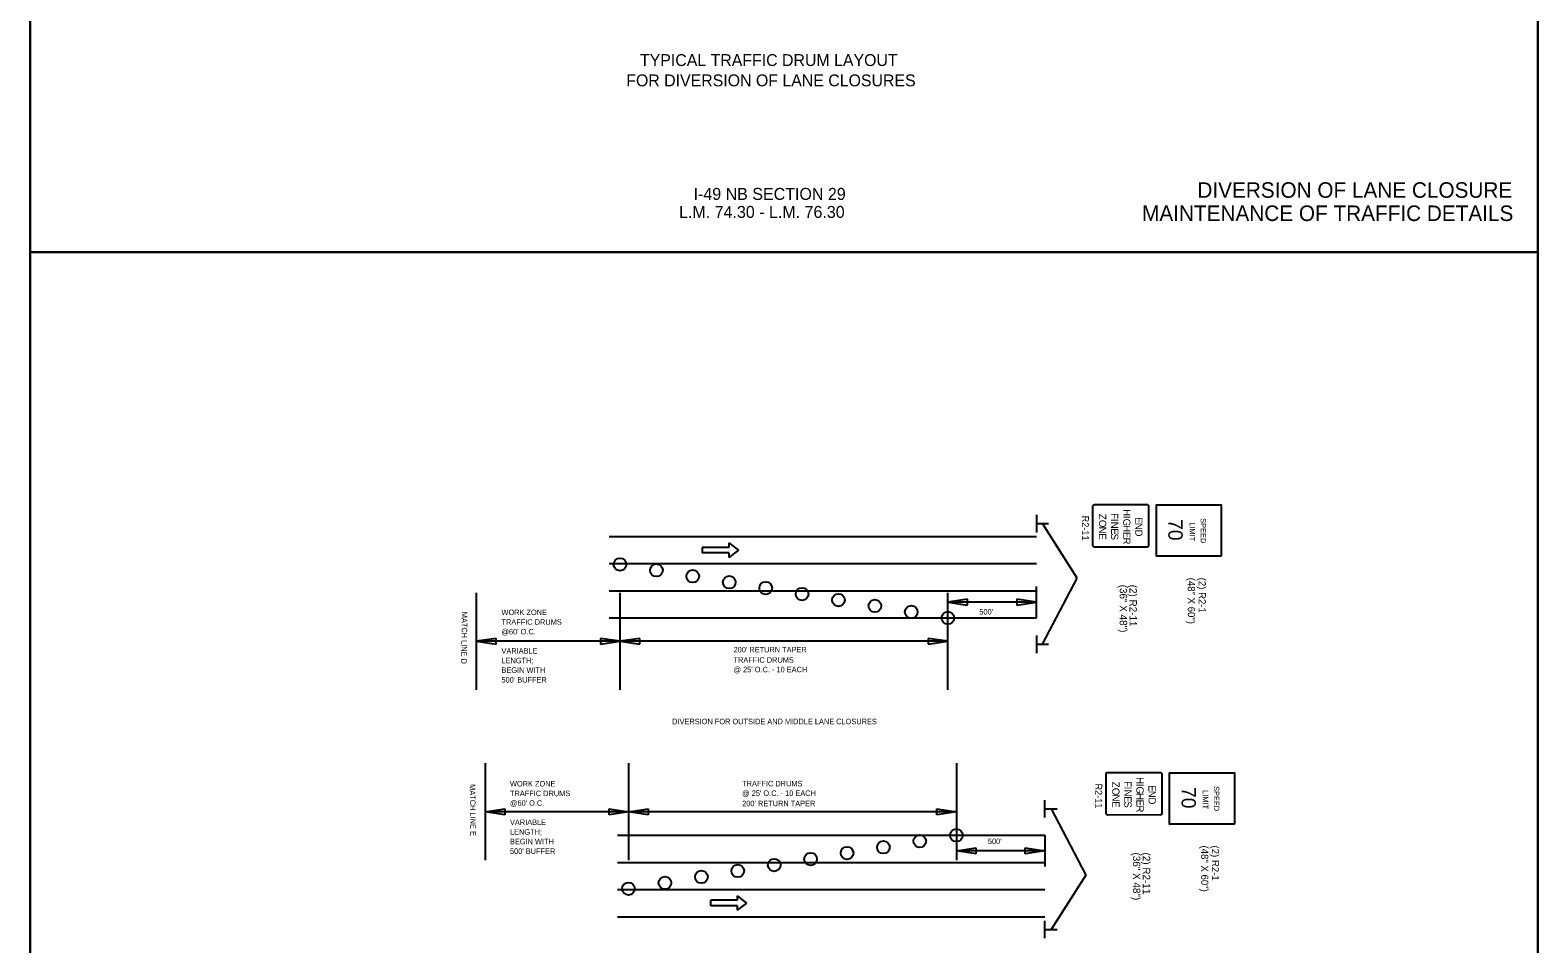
# Model space of a CAD drawing. Extents: x -100 to 745, y -1581 to -107.
# Drawn here: x 175.4 to 345.4, y -1108.6 to -1005.6 of the extents above; entities that cross this region are included whole.
import ezdxf

# ---------------------------------------------------------------- set-up
doc = ezdxf.new("R2010")
doc.units = 0
for name, color, linetype in [('Default', 7, 'Continuous'), ('R_Contour Annot', 7, 'Continuous'), ('R_Draft', 7, 'Continuous'), ('R_MOT', 7, 'Continuous')]:
    doc.layers.add(name, color=color, linetype=linetype)

msp = doc.modelspace()

# ---------------------------------------------------------------- linework, layer by layer
at = {"layer": 'Default'}
for p, q in [((301.34, -1059.09), (295.41, -1059.09)), ((288.86, -1060.23), (288.86, -1062.21)), ((295.19, -1059.32), (295.19, -1063.61)), ((301.56, -1063.6), (301.56, -1059.31)), ((288.89, -1061.21), (290.24, -1061.21)), ((293.47, -1067.36), (289.57, -1061.21)), ((240.69, -1062.66), (288.86, -1062.66)), ((254.19, -1063.9), (251.18, -1063.9)), ((251.18, -1063.9), (251.18, -1064.51)), ((254.19, -1063.38), (254.19, -1063.9)), ((254.19, -1063.38), (255.26, -1064.2)), ((295.41, -1063.83), (301.34, -1063.83)), ((240.69, -1065.72), (288.86, -1065.72)), ((254.19, -1064.51), (251.18, -1064.51)), ((255.26, -1064.2), (254.19, -1065.02)), ((254.19, -1064.51), (254.19, -1065.02)), ((289.57, -1074.82), (293.47, -1067.36)), ((225.74, -1079.95), (225.74, -1069.02)), ((240.69, -1068.78), (288.86, -1068.78)), ((241.93, -1079.95), (241.93, -1069.02)), ((278.88, -1079.95), (278.88, -1069.02)), ((288.86, -1071.85), (288.86, -1068.32)), ((281.09, -1069.75), (278.88, -1070.08)), ((278.88, -1070.08), (281.09, -1070.41)), ((288.86, -1070.08), (278.88, -1070.08)), ((281.09, -1070.41), (281.09, -1069.75)), ((288.86, -1070.08), (286.65, -1069.75)), ((286.65, -1069.75), (286.65, -1070.41)), ((286.65, -1070.41), (288.86, -1070.08)), ((240.69, -1071.85), (288.86, -1071.85)), ((227.94, -1074.16), (225.74, -1074.49)), ((227.94, -1074.82), (227.94, -1074.16)), ((241.93, -1074.49), (239.72, -1074.16)), ((239.72, -1074.16), (239.72, -1074.82)), ((244.14, -1074.16), (241.93, -1074.49)), ((244.14, -1074.82), (244.14, -1074.16)), ((278.88, -1074.49), (276.67, -1074.16)), ((276.67, -1074.16), (276.67, -1074.82)), ((288.86, -1073.83), (288.86, -1075.82)), ((241.93, -1074.49), (225.74, -1074.49)), ((225.74, -1074.49), (227.94, -1074.82)), ((239.72, -1074.82), (241.93, -1074.49)), ((278.88, -1074.49), (241.93, -1074.49)), ((241.93, -1074.49), (244.14, -1074.82)), ((276.67, -1074.82), (278.88, -1074.49)), ((288.89, -1074.82), (290.24, -1074.82)), ((226.7, -1088.25), (226.7, -1099.19)), ((242.89, -1088.25), (242.89, -1099.19)), ((279.85, -1088.25), (279.85, -1099.19)), ((296.68, -1089.53), (296.69, -1093.83)), ((302.83, -1089.31), (296.9, -1089.31)), ((303.06, -1093.82), (303.05, -1089.53)), ((289.82, -1094.37), (289.82, -1092.39)), ((226.7, -1093.72), (228.91, -1093.39)), ((242.89, -1093.72), (226.7, -1093.72)), ((228.91, -1094.05), (226.7, -1093.72)), ((228.91, -1093.39), (228.91, -1094.05)), ((240.69, -1094.05), (240.69, -1093.39)), ((240.69, -1093.39), (242.89, -1093.72)), ((242.89, -1093.72), (240.69, -1094.05)), ((242.89, -1093.72), (245.1, -1093.39)), ((279.85, -1093.72), (242.89, -1093.72)), ((245.1, -1094.05), (242.89, -1093.72)), ((245.1, -1093.39), (245.1, -1094.05)), ((277.64, -1094.05), (277.64, -1093.39)), ((277.64, -1093.39), (279.85, -1093.72)), ((279.85, -1093.72), (277.64, -1094.05)), ((289.85, -1093.38), (291.21, -1093.38)), ((290.53, -1093.38), (294.44, -1100.85)), ((296.91, -1094.05), (302.84, -1094.04)), ((241.65, -1096.36), (289.82, -1096.36)), ((289.83, -1096.36), (289.83, -1099.89)), ((279.85, -1098.12), (282.05, -1097.79)), ((282.05, -1098.46), (279.85, -1098.12)), ((289.82, -1098.12), (279.85, -1098.12)), ((282.05, -1097.79), (282.05, -1098.46)), ((287.61, -1098.46), (287.61, -1097.79)), ((287.61, -1097.79), (289.82, -1098.12)), ((289.82, -1098.12), (287.61, -1098.46)), ((241.65, -1099.42), (289.83, -1099.42)), ((294.44, -1100.85), (290.53, -1106.99)), ((241.65, -1102.49), (289.83, -1102.49)), ((255.16, -1103.7), (255.16, -1103.19)), ((256.22, -1104.01), (255.16, -1103.19)), ((255.16, -1103.7), (252.15, -1103.7)), ((252.15, -1104.31), (252.15, -1103.7)), ((255.16, -1104.31), (252.15, -1104.31)), ((255.16, -1104.82), (256.22, -1104.01)), ((255.16, -1104.82), (255.16, -1104.31)), ((241.65, -1105.55), (289.83, -1105.55)), ((289.82, -1107.98), (289.82, -1106)), ((289.85, -1106.99), (291.21, -1106.99))]:
    msp.add_line(p, q, dxfattribs=at)
for points in [[(309.7, -1064.89), (302.39, -1064.89), (302.39, -1059.09), (309.7, -1059.09)], [(311.2, -1095.11), (303.89, -1095.11), (303.89, -1089.31), (311.2, -1089.31)]]:
    msp.add_lwpolyline(points, close=True, dxfattribs=at)
for centre in [(241.91, -1065.81), (246.02, -1066.48), (250.12, -1067.15), (254.23, -1067.82), (258.34, -1068.49), (262.44, -1069.16), (266.55, -1069.83), (270.65, -1070.5), (274.76, -1071.17), (278.88, -1071.85), (275.72, -1097.03), (279.85, -1096.36), (267.51, -1098.38), (271.62, -1097.71), (255.19, -1100.39), (259.3, -1099.72), (263.41, -1099.05), (246.98, -1101.73), (251.09, -1101.06), (242.87, -1102.4)]:
    msp.add_circle(centre, 0.714, dxfattribs=at)
for centre, start, end in [((295.41, -1059.32), 90.0457, 180.0457), ((301.34, -1059.31), 0.0457, 90.0457), ((295.41, -1063.61), 180.0457, 270.0457), ((301.34, -1063.6), 270.0457, 0.0457), ((296.9, -1089.53), 90.0457, 180.0457), ((302.83, -1089.53), 0.0457, 90.0457), ((296.91, -1093.83), 180.0457, 270.0457), ((302.84, -1093.82), 270.0457, 0.0457)]:
    msp.add_arc(centre, 0.221, start, end, dxfattribs=at)
at = {"layer": 'R_Contour Annot'}
for points in [[(175.41, -920.58), (345.41, -920.58), (345.41, -1030.58), (175.41, -1030.58)], [(175.41, -1030.58), (345.41, -1030.58), (345.41, -1140.58), (175.41, -1140.58)]]:
    msp.add_lwpolyline(points, close=True, dxfattribs=at)
at = {"layer": 'R_Draft'}
for points in [[(175.41, -920.58), (175.41, -1030.58), (345.41, -1030.58), (345.41, -920.58)], [(175.41, -1030.58), (175.41, -1140.58), (345.41, -1140.58), (345.41, -1030.58)]]:
    msp.add_lwpolyline(points, close=True, dxfattribs=at)

# ---------------------------------------------------------------- texts
at = {"layer": 'Default'}
for s, height, p in [('TYPICAL TRAFFIC DRUM LAYOUT', 1.3388, (244.17, -1009.6)), ('FOR DIVERSION OF LANE CLOSURES', 1.3388, (242.62, -1011.89)), ('I-49 NB SECTION 29', 1.35, (250.21, -1024.7)), ('L.M. 74.30 - L.M. 76.30', 1.35, (248.58, -1026.73)), ('WORK ZONE', 0.622, (228.55, -1071.53)), ("500'", 0.622, (282.43, -1071.47)), ('TRAFFIC DRUMS ', 0.6222, (228.55, -1072.62)), ("@60' O.C.", 0.622, (228.55, -1073.71)), ('VARIABLE', 0.622, (228.55, -1075.88)), ("200' RETURN TAPER", 0.6222, (254.72, -1075.74)), ('LENGTH;', 0.622, (228.55, -1076.97)), ('BEGIN WITH', 0.622, (228.55, -1078.05)), ('TRAFFIC DRUMS', 0.6222, (254.72, -1076.9)), ("@ 25' O.C. - 10 EACH", 0.6222, (254.72, -1077.98)), ("500' BUFFER", 0.6222, (228.55, -1079.14)), ('DIVERSION FOR OUTSIDE AND MIDDLE LANE CLOSURES', 0.6222, (247.8, -1083.84)), ('WORK ZONE', 0.622, (229.51, -1090.86)), ('TRAFFIC DRUMS ', 0.6222, (229.51, -1091.95)), ('TRAFFIC DRUMS', 0.6222, (255.69, -1090.85)), ("@ 25' O.C. - 10 EACH", 0.6222, (255.69, -1091.93)), ("@60' O.C.", 0.622, (229.51, -1093.04)), ("200' RETURN TAPER", 0.6222, (255.69, -1093.09)), ('VARIABLE', 0.622, (229.51, -1095.21)), ('LENGTH;', 0.622, (229.51, -1096.3)), ("500' BUFFER", 0.6222, (229.51, -1098.47)), ('BEGIN WITH', 0.622, (229.51, -1097.38)), ("500'", 0.622, (283.4, -1097.36))]:
    msp.add_text(s, height=height, dxfattribs=at).set_placement(p)
for s, height, rotation, p in [('R2-11', 0.771, 270.0457, (294.01, -1060.31)), ('Z', 0.818, 270.0457, (295.92, -1060.11)), ('F', 0.818, 270.0457, (297.28, -1060.03)), ('I', 0.818, 270.0457, (297.29, -1060.66)), ('G', 0.818, 270.0457, (298.65, -1060.65)), ('H', 0.818, 270.0457, (298.65, -1059.58)), ('I', 0.818, 270.0457, (298.65, -1060.33)), ('E', 0.818, 270.0457, (300.01, -1060.48)), ('SPEED', 0.604, 270, (307.38, -1060.6)), ('O', 0.818, 270.0457, (295.92, -1060.79)), ('N', 0.818, 270.0457, (295.92, -1061.55)), ('E', 0.818, 270.0457, (295.92, -1062.31)), ('S', 0.818, 270.0457, (297.29, -1062.33)), ('N', 0.818, 270.0457, (297.29, -1060.99)), ('E', 0.818, 270.0457, (297.29, -1061.74)), ('H', 0.818, 270.0457, (298.65, -1061.38)), ('E', 0.818, 270.0457, (298.65, -1062.14)), ('N', 0.818, 270.0457, (300.01, -1061.13)), ('D', 0.818, 270.0457, (300.01, -1061.88)), ('70', 1.62, 270, (303.74, -1060.71)), ('LIMIT', 0.604, 270, (306.14, -1061.06)), ('R', 0.818, 270.0457, (298.65, -1062.78)), ('(48" X 60")', 0.8098, 270, (305.94, -1067.31)), ('(2) R2-1', 0.81, 270, (307.16, -1067.31)), ('(36" X 48")', 0.8349, 270.0457, (298.26, -1068.1)), ('(2) R2-11', 0.835, 270.0457, (299.36, -1068.1)), ('MATCH LINE D', 0.6222, 269.1941, (224.09, -1071.16)), ('MATCH LINE E', 0.6222, 270.8059, (224.97, -1090.61)), ('R2-11', 0.771, 270.0457, (295.51, -1090.53)), ('O', 0.818, 270.0457, (297.42, -1091.01)), ('Z', 0.818, 270.0457, (297.42, -1090.33)), ('F', 0.818, 270.0457, (298.78, -1090.25)), ('I', 0.818, 270.0457, (298.78, -1090.88)), ('N', 0.818, 270.0457, (298.78, -1091.21)), ('G', 0.818, 270.0457, (300.14, -1090.86)), ('H', 0.818, 270.0457, (300.14, -1089.8)), ('I', 0.818, 270.0457, (300.14, -1090.55)), ('E', 0.818, 270.0457, (301.5, -1090.7)), ('70', 1.62, 270, (305.23, -1090.93)), ('LIMIT', 0.604, 270, (307.63, -1091.28)), ('SPEED', 0.604, 270, (308.88, -1090.82)), ('N', 0.818, 270.0457, (297.42, -1091.77)), ('E', 0.818, 270.0457, (297.42, -1092.52)), ('S', 0.818, 270.0457, (298.78, -1092.55)), ('E', 0.818, 270.0457, (298.78, -1091.96)), ('H', 0.818, 270.0457, (300.14, -1091.6)), ('E', 0.818, 270.0457, (300.14, -1092.35)), ('R', 0.818, 270.0457, (300.14, -1093)), ('N', 0.818, 270.0457, (301.51, -1091.34)), ('D', 0.818, 270.0457, (301.51, -1092.1)), ('(48" X 60")', 0.8098, 270, (307.44, -1097.52)), ('(2) R2-1', 0.81, 270, (308.65, -1097.52)), ('(36" X 48")', 0.8349, 270.0457, (299.75, -1098.31)), ('(2) R2-11', 0.835, 270.0457, (300.86, -1098.31))]:
    msp.add_text(s, height=height, rotation=rotation, dxfattribs=at).set_placement(p)
at = {"layer": 'R_MOT'}
for s, p in [('DIVERSION OF LANE CLOSURE', (307.02, -1024.46)), ('MAINTENANCE OF TRAFFIC DETAILS', (300.78, -1027.08))]:
    msp.add_text(s, height=1.75, dxfattribs=at).set_placement(p)

doc.saveas('drawing.dxf')
